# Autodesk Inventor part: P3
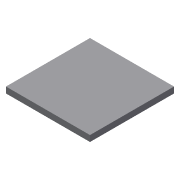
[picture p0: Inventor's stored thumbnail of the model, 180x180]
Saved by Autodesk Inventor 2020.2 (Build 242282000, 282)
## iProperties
Created: 2005-11
Part Number: P3
Document SubType Name: Modeling
Designer: F.Stasiak
Density: 1 g/cm^3
Material: Ogólny
Appearance: Domyślna
Manager: www.cadconsulting.pl
Company: Fabian Stasiak CAD Consulting
Author: F.Stasiak
Subject: Zbiór ćwiczeń. Autodesk Inventor 2020. Kurs podstawowy
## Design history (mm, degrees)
sketch "Szkic1"
  geometry: L1 (70, 70)-(70, -70); L2 (70, -70)-(-70, -70); L3 (-70, -70)-(-70, 70); L4 (-70, 70)-(70, 70); 2 further points
  constraints: 8 end point, 1 coincident, 7 other
  dimensions: "d0" = 140 distance of L1.end L2.end
extrude "Wyciągnięcie proste1" new body sketch "Szkic1" distance "d1" = 10; taper "d2" = 0 deg
node "Bryła1"
node "Korpusy bryłowe"
node "Korpusy powierzchniowe"
